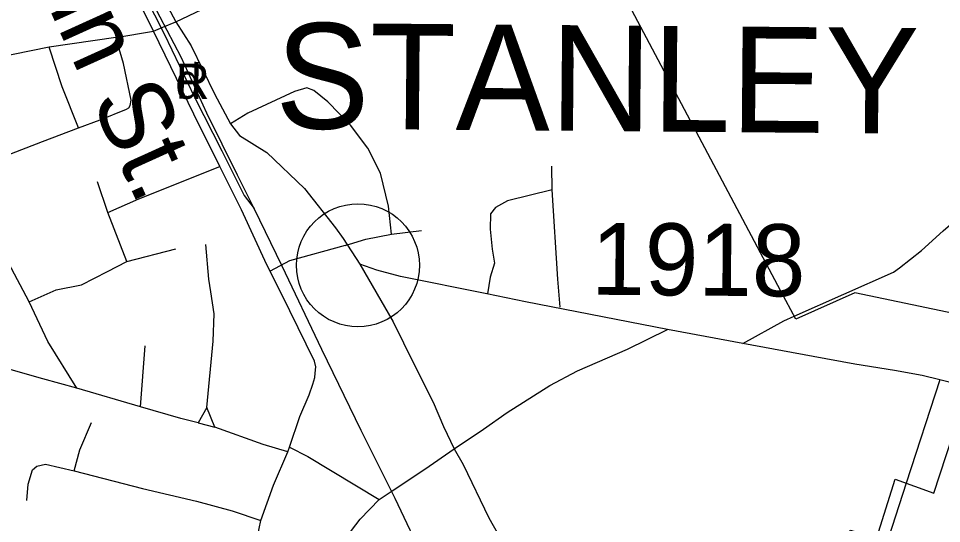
# Model space of a CAD drawing. Extents: x 1379453 to 1387082, y 594364 to 596664.
# Drawn here: x 1380115.2 to 1380304.5, y 596077 to 596180.5 of the extents above; entities that cross this region are included whole.
import ezdxf

# ---------------------------------------------------------------- set-up
doc = ezdxf.new("R2010")
doc.units = 0
for name, color, linetype in [('Old_Level_11', 7, 'Continuous'), ('Old_Level_29', 7, 'Continuous'), ('Old_Level_32', 7, 'Continuous'), ('Old_Level_35', 7, 'Continuous'), ('Old_Level_44', 7, 'Continuous'), ('Old_Level_48', 7, 'Continuous'), ('Old_Level_49', 7, 'Continuous'), ('Old_Level_8', 7, 'Continuous'), ('Old_Level_9', 7, 'Continuous')]:
    doc.layers.add(name, color=color, linetype=linetype)

msp = doc.modelspace()

# ---------------------------------------------------------------- linework, layer by layer
at = {"layer": 'Old_Level_29'}
for p, q in [((1380142.92, 596177.94), (1380144.85, 596178.73)), ((1380144.85, 596178.73), (1380147.53, 596179.82))]:
    msp.add_line(p, q, dxfattribs=at)
for points in [[(1380133.91, 596206.95), (1380136.38, 596201.11), (1380140.4, 596193.23), (1380147.53, 596179.82)], [(1380147.53, 596179.82), (1380150.64, 596174.93), (1380155.43, 596165.09), (1380158.69, 596158.91), (1380160.54, 596156.53), (1380166.15, 596153.05), (1380173.87, 596145.66), (1380180.22, 596137.59), (1380181.79, 596135.39), (1380185.21, 596130.17)], [(1380160.02, 596042.03), (1380160.83, 596049.23), (1380161.44, 596052.59), (1380162.72, 596063.05), (1380163.55, 596071.03), (1380164.94, 596077.63), (1380167.52, 596084.82), (1380170.44, 596091.69), (1380170.78, 596092.66), (1380172.95, 596098.94), (1380174.87, 596103.36), (1380175.61, 596105.57), (1380176, 596106.91), (1380176.05, 596107.79), (1380176.21, 596109.13), (1380175.94, 596110.29), (1380170.86, 596120.61), (1380166.84, 596128.69), (1380166.18, 596130.03), (1380160.98, 596141.31), (1380156.51, 596150.17), (1380151.21, 596160.9), (1380142.92, 596177.94)], [(1380185.21, 596130.17), (1380192.06, 596118.33), (1380196.29, 596109.69), (1380200.23, 596101.87), (1380202.37, 596096.87), (1380204.53, 596092.33)], [(1380204.53, 596092.33), (1380206.39, 596089.06), (1380211.66, 596078.14), (1380223.88, 596056.55), (1380234.7, 596039.29), (1380241.97, 596028.31), (1380246.45, 596022.15), (1380262.87, 596000.58), (1380263.77, 595999.32), (1380268.91, 595993.22), (1380274.88, 595986.84), (1380280.62, 595980.44), (1380286.53, 595974.34), (1380294.69, 595966.17), (1380301.61, 595958.93), (1380328.88, 595933.24), (1380339.13, 595925.25), (1380353.32, 595914.75), (1380366.47, 595904.76), (1380375.33, 595898.26), (1380418.73, 595865.44)]]:
    msp.add_lwpolyline(points, dxfattribs=at)
at = {"layer": 'Old_Level_32'}
msp.add_line((1380263.73, 596113.86), (1380248.31, 596116.76), dxfattribs=at)
for points in [[(1380129.39, 596205.72), (1380136.89, 596189.9), (1380142.92, 596177.94)], [(1380263.73, 596113.86), (1380272.14, 596118.56), (1380274.24, 596119.51), (1380294.66, 596128.5), (1380295.83, 596129.38), (1380300.37, 596132.98), (1380304.84, 596137.02), (1380318.44, 596148.73), (1380324.65, 596153.76)], [(1380248.31, 596116.76), (1380219.2, 596122.45), (1380211.29, 596124.1), (1380193.57, 596127.65), (1380188.68, 596128.9), (1380185.21, 596130.17)], [(1380204.53, 596092.33), (1380210.6, 596096.36), (1380215.46, 596099.72), (1380224.19, 596105.31), (1380229.84, 596108.31), (1380240.07, 596112.76), (1380248.31, 596116.76)], [(1380304.16, 596106.46), (1380300.48, 596107.3), (1380294.86, 596108.37), (1380286.71, 596109.66), (1380278.15, 596111.25), (1380263.73, 596113.86)], [(1380304.16, 596106.46), (1380297.25, 596085.24), (1380291.39, 596067.26)], [(1380353.18, 596100.29), (1380341.18, 596100.88), (1380325.63, 596101.53), (1380319.96, 596101.74), (1380316.71, 596102.26), (1380313.19, 596103.57), (1380307.61, 596105.53), (1380304.16, 596106.46)], [(1380191.65, 596083.54), (1380198.58, 596088.13), (1380204.53, 596092.33)], [(1380160.02, 596042.03), (1380163.22, 596043.56), (1380164.18, 596044.15), (1380164.8, 596044.84), (1380165.72, 596046.22), (1380168.14, 596050.27), (1380170.85, 596055.06), (1380177.14, 596066.38), (1380180.71, 596071.72), (1380183.51, 596075.58), (1380185.3, 596077.91), (1380189.19, 596081.92), (1380191.65, 596083.54)]]:
    msp.add_lwpolyline(points, dxfattribs=at)
msp.add_circle((1380184.84, 596129.92), 12.61, dxfattribs=at)
at = {"layer": 'Old_Level_35'}
for p, q in [((1380135.19, 596176.65), (1380142.92, 596177.94)), ((1380135.19, 596176.65), (1380121.52, 596174.65)), ((1380224.66, 596145.38), (1380224.57, 596150.26)), ((1380133.59, 596140.75), (1380131.43, 596147.05)), ((1380137.45, 596130.71), (1380133.59, 596140.75)), ((1380191.73, 596136.33), (1380197.84, 596137.03)), ((1380137.45, 596130.71), (1380147.48, 596133.33)), ((1380117.43, 596122.41), (1380113.19, 596130.46)), ((1380140.27, 596100.93), (1380141.19, 596113.39)), ((1380140.27, 596100.93), (1380127.21, 596104.73)), ((1380153.87, 596100.77), (1380152.1, 596097.62)), ((1380155.52, 596096.72), (1380153.87, 596100.77)), ((1380152.1, 596097.62), (1380155.52, 596096.72))]:
    msp.add_line(p, q, dxfattribs=at)
for points in [[(1380147.53, 596179.82), (1380192.75, 596201.39), (1380200.14, 596204.85)], [(1380127.52, 596158.14), (1380131.97, 596159.77), (1380137.4, 596161.93), (1380137.89, 596162.24), (1380138.14, 596162.71), (1380138.34, 596163.75), (1380136.79, 596171.31), (1380135.19, 596176.65)], [(1380121.52, 596174.65), (1380095.98, 596169.47), (1380090.26, 596168.4), (1380086.79, 596168.3), (1380084.62, 596169.32)], [(1380127.52, 596158.14), (1380124.17, 596166.48), (1380121.52, 596174.65)], [(1380191.73, 596136.33), (1380191.1, 596142.03), (1380189.46, 596148.81), (1380186.89, 596153.92), (1380183.34, 596158.67), (1380178.68, 596163.45), (1380175.78, 596165.78), (1380174.36, 596166.3), (1380171.86, 596165.58), (1380162.28, 596161.13), (1380158.69, 596158.91)], [(1380106.15, 596149.88), (1380120.16, 596155.31), (1380127.52, 596158.14)], [(1380133.59, 596140.75), (1380139.91, 596143.53), (1380156.51, 596150.17)], [(1380224.66, 596145.38), (1380215.47, 596143.16), (1380213.03, 596141.8), (1380212.03, 596140.46), (1380211.94, 596137.34), (1380212.38, 596133.25), (1380212.85, 596130.36), (1380211.92, 596127.5), (1380211.4, 596124.08)], [(1380226.28, 596121.33), (1380225.81, 596127.09), (1380224.66, 596145.38)], [(1380182.22, 596133.97), (1380186.42, 596135.28), (1380191.73, 596136.33)], [(1380153.87, 596100.77), (1380155.18, 596114.35), (1380155.33, 596119.99), (1380154.65, 596124.48), (1380154.29, 596127.07), (1380153.63, 596134.2)], [(1380182.22, 596133.97), (1380170.8, 596130.82), (1380166.84, 596128.69)], [(1380117.43, 596122.41), (1380122.95, 596124.89), (1380128.19, 596125.94), (1380133.47, 596128.64), (1380137.45, 596130.71)], [(1380127.21, 596104.73), (1380121.29, 596114.31), (1380117.43, 596122.41)], [(1380127.21, 596104.73), (1380120.26, 596106.64), (1380106.05, 596110.65)], [(1380152.1, 596097.62), (1380148.53, 596098.52), (1380140.27, 596100.93)], [(1380126.68, 596087.79), (1380127.84, 596092.08), (1380130.24, 596097.7)], [(1380170.44, 596091.69), (1380165.4, 596093.17), (1380155.52, 596096.72)], [(1380170.78, 596092.66), (1380174.56, 596090.72), (1380189.19, 596081.92)], [(1380116.97, 596081.68), (1380117.23, 596085.03), (1380118.12, 596087.97), (1380119.02, 596088.74), (1380120.8, 596089.16), (1380126.68, 596087.79)], [(1380126.68, 596087.79), (1380140.66, 596084.18), (1380151.71, 596081.54), (1380159.02, 596079.56), (1380164.94, 596077.63)]]:
    msp.add_lwpolyline(points, dxfattribs=at)
at = {"layer": 'Old_Level_44'}
for points in [[(1380198.66, 596068.96), (1380192.47, 596082.12), (1380185.52, 596096.08), (1380177.44, 596112.65), (1380169.29, 596129.78), (1380163.55, 596141.56), (1380160.14, 596148.38), (1380153.87, 596161.13), (1380148.6, 596172.57), (1380142.84, 596183.55), (1380137.1, 596195.32), (1380131.3, 596207.98), (1380125.99, 596217.98), (1380123.06, 596224.56), (1380121.05, 596229.82), (1380118.64, 596237.81), (1380116.06, 596248.21), (1380112.78, 596261.93)], [(1380163.55, 596141.56), (1380160.14, 596148.38), (1380153.87, 596161.13), (1380148.6, 596172.57), (1380142.84, 596183.55), (1380137.1, 596195.32), (1380131.3, 596207.98), (1380125.99, 596217.98), (1380123.06, 596224.56), (1380121.05, 596229.82), (1380118.64, 596237.81), (1380116.06, 596248.21)], [(1380116.06, 596248.21), (1380116.64, 596243.07), (1380118.43, 596235.9), (1380120.62, 596228.71), (1380122.93, 596223.04), (1380125.71, 596216.71), (1380129.8, 596208.59), (1380134.17, 596199.34), (1380139.09, 596189.26), (1380145.14, 596177.4), (1380151.41, 596164.24), (1380156.93, 596153.36), (1380161.54, 596144.25), (1380163.55, 596141.56)], [(1380312.9, 595909.53), (1380300.13, 595919.1), (1380289.32, 595927.58), (1380279.3, 595935), (1380272.41, 595940.8), (1380263.17, 595950.44), (1380258.61, 595955.93), (1380253.98, 595961.92), (1380249.35, 595968.05), (1380244.35, 595975.08), (1380239.89, 595983.7), (1380234.97, 595993.77), (1380229, 596006.04), (1380220.69, 596022.93), (1380213.97, 596036.66), (1380206.29, 596053.29), (1380198.66, 596068.96), (1380192.47, 596082.12), (1380185.52, 596096.08), (1380177.44, 596112.65), (1380169.29, 596129.78), (1380163.55, 596141.56)]]:
    msp.add_lwpolyline(points, dxfattribs=at)
at = {"layer": 'Old_Level_48'}
msp.add_lwpolyline([(1380306.1, 595961.49), (1380283.01, 595983.98), (1380282.74, 595991.87), (1380288.32, 596012.89), (1380266.64, 596016.44), (1380270.23, 596027.03), (1380285.74, 596075.63), (1380291.22, 596074.09), (1380294.95, 596086.05), (1380302.91, 596083.24), (1380314.44, 596118.5), (1380286.73, 596124.3), (1380274.6, 596118.89), (1380271.54, 596124.6), (1380193.74, 596271.38), (1380220.87, 596276.59), (1380219.29, 596281.97), (1380217.17, 596306.95), (1380216.79, 596311.89), (1380184.45, 596305.78), (1380172.72, 596328.84)], dxfattribs=at)
at = {"layer": 'Old_Level_49'}
msp.add_lwpolyline([(1380306.1, 595961.49), (1380283.01, 595983.98), (1380282.74, 595991.87), (1380288.32, 596012.89), (1380266.64, 596016.44), (1380270.23, 596027.03), (1380285.74, 596075.63), (1380291.22, 596074.09), (1380294.95, 596086.05), (1380302.91, 596083.24), (1380314.44, 596118.5), (1380286.73, 596124.3), (1380274.6, 596118.89), (1380271.54, 596124.6), (1380193.74, 596271.38), (1380220.87, 596276.59), (1380219.29, 596281.97), (1380217.17, 596306.95), (1380216.79, 596311.89), (1380184.45, 596305.78), (1380172.72, 596328.84)], dxfattribs=at)

# ---------------------------------------------------------------- texts
at = {"layer": 'Old_Level_11'}
msp.add_text('North Main St.', height=14.7638, rotation=294.3805, dxfattribs=at).set_placement((1380087.91, 596256.7))
at = {"layer": 'Old_Level_8'}
msp.add_text('1918', height=14.764, rotation=359.52, dxfattribs=at).set_placement((1380232.61, 596123.9))
at = {"layer": 'Old_Level_9'}
for s, height, p in [('STANLEY', 21.653, (1380167.83, 596158.01)), ('d', 7.22, (1380147.39, 596164.07)), ('R', 7.22, (1380147.43, 596164.07))]:
    msp.add_text(s, height=height, rotation=359.52, dxfattribs=at).set_placement(p)

doc.saveas('drawing.dxf')
